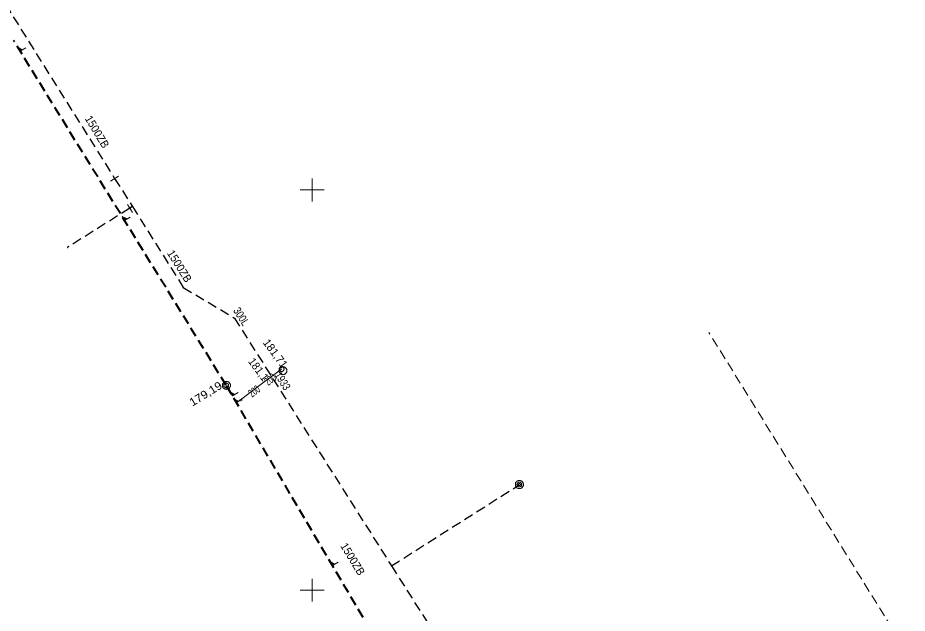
# Model space of a CAD drawing. Extents: x -740851 to -738888, y -1041382 to -1040235.
# Drawn here: x -739386.8 to -739275.6, y -1041102.9 to -1041028.5 of the extents above; entities that cross this region are included whole.
import ezdxf

# ---------------------------------------------------------------- set-up
doc = ezdxf.new("R2010")
doc.units = 0
doc.header["$LTSCALE"] = 0.4
doc.linetypes.add('MEDIUM_DASHED', pattern=[4.5, 3, -1.5])
for name, color, linetype, lineweight in [('1', 7, 'Continuous', 13), ('18', 7, 'Continuous', 13), ('38', 7, 'Continuous', 13), ('49', 7, 'Continuous', 13), ('8', 7, 'Continuous', 13)]:
    doc.layers.add(name, color=color, linetype=linetype, lineweight=lineweight)

msp = doc.modelspace()

# ---------------------------------------------------------------- linework, layer by layer
at = {"layer": '1'}
for p, q in [((-739350, -1041048.571), (-739350, -1041051.429)), ((-739351.48, -1041050), (-739348.48, -1041050)), ((-739350, -1041098.571), (-739350, -1041101.429)), ((-739351.48, -1041100), (-739348.48, -1041100))]:
    msp.add_line(p, q, dxfattribs=at)
at = {"layer": '18', "linetype": 'MEDIUM_DASHED', "lineweight": 40}
for p, q in [((-739360.74, -1041074.41), (-739387.32, -1041031.31)), ((-739332.66, -1041122.02), (-739360.74, -1041074.41))]:
    msp.add_line(p, q, dxfattribs=at)
at = {"layer": '18'}
for p, q in [((-739359.047, -1041076.171), (-739358.717, -1041076.255)), ((-739358.832, -1041076.051), (-739358.918, -1041076.384))]:
    msp.add_line(p, q, dxfattribs=at)
for points in [[(-739385.785, -1041032.241), (-739386.479, -1041032.669), (-739386.785, -1041032.174), (-739386.166, -1041032.476)], [(-739386.258, -1041032.482), (-739386.461, -1041032.607), (-739386.656, -1041032.291), (-739386.256, -1041032.486)], [(-739386.354, -1041032.491), (-739386.455, -1041032.553), (-739386.555, -1041032.391), (-739386.352, -1041032.494)], [(-739372.741, -1041053.392), (-739373.435, -1041053.82), (-739373.741, -1041053.325), (-739373.122, -1041053.627)], [(-739373.214, -1041053.634), (-739373.417, -1041053.758), (-739373.612, -1041053.442), (-739373.212, -1041053.637)], [(-739373.31, -1041053.642), (-739373.411, -1041053.705), (-739373.511, -1041053.542), (-739373.308, -1041053.646)], [(-739359.248, -1041075.327), (-739359.952, -1041075.742), (-739360.248, -1041075.24), (-739359.634, -1041075.555)], [(-739359.727, -1041075.56), (-739359.932, -1041075.681), (-739360.121, -1041075.36), (-739359.725, -1041075.563)], [(-739359.822, -1041075.566), (-739359.925, -1041075.627), (-739360.022, -1041075.462), (-739359.821, -1041075.57)], [(-739358.875, -1041076.214), (-739359.468, -1041076.564), (-739359.717, -1041076.141), (-739359.2, -1041076.406)], [(-739359.278, -1041076.41), (-739359.451, -1041076.512), (-739359.61, -1041076.242), (-739359.276, -1041076.413)], [(-739359.359, -1041076.416), (-739359.445, -1041076.467), (-739359.527, -1041076.328), (-739359.357, -1041076.419)], [(-739346.751, -1041096.516), (-739347.455, -1041096.932), (-739347.751, -1041096.429), (-739347.137, -1041096.744)], [(-739347.23, -1041096.749), (-739347.435, -1041096.87), (-739347.624, -1041096.549), (-739347.228, -1041096.752)], [(-739347.325, -1041096.756), (-739347.428, -1041096.816), (-739347.525, -1041096.651), (-739347.323, -1041096.759)]]:
    msp.add_lwpolyline(points, dxfattribs=at)
for points in [[(-739353.14, -1041072.58), (-739353.15, -1041072.53), (-739353.15, -1041072.48), (-739353.17, -1041072.43), (-739353.19, -1041072.38), (-739353.21, -1041072.33), (-739353.24, -1041072.29), (-739353.27, -1041072.25), (-739353.31, -1041072.21), (-739353.35, -1041072.18), (-739353.39, -1041072.15), (-739353.44, -1041072.13), (-739353.49, -1041072.11), (-739353.54, -1041072.09), (-739353.59, -1041072.09), (-739353.64, -1041072.08), (-739353.69, -1041072.09), (-739353.74, -1041072.09), (-739353.79, -1041072.11), (-739353.84, -1041072.13), (-739353.89, -1041072.15), (-739353.93, -1041072.18), (-739353.97, -1041072.21), (-739354.01, -1041072.25), (-739354.04, -1041072.29), (-739354.07, -1041072.33), (-739354.09, -1041072.38), (-739354.11, -1041072.43), (-739354.13, -1041072.48), (-739354.13, -1041072.53), (-739354.14, -1041072.58), (-739354.13, -1041072.63), (-739354.13, -1041072.68), (-739354.11, -1041072.73), (-739354.09, -1041072.78), (-739354.07, -1041072.83), (-739354.04, -1041072.87), (-739354.01, -1041072.91), (-739353.97, -1041072.95), (-739353.93, -1041072.98), (-739353.89, -1041073.01), (-739353.84, -1041073.03), (-739353.79, -1041073.05), (-739353.74, -1041073.07), (-739353.69, -1041073.07), (-739353.64, -1041073.08), (-739353.59, -1041073.07), (-739353.54, -1041073.07), (-739353.49, -1041073.05), (-739353.44, -1041073.03), (-739353.39, -1041073.01), (-739353.35, -1041072.98), (-739353.31, -1041072.95), (-739353.27, -1041072.91), (-739353.24, -1041072.87), (-739353.21, -1041072.83), (-739353.19, -1041072.78), (-739353.17, -1041072.73), (-739353.15, -1041072.68), (-739353.15, -1041072.63)], [(-739353.51, -1041072.38), (-739353.51, -1041072.35), (-739353.516, -1041072.32), (-739353.522, -1041072.29), (-739353.534, -1041072.26), (-739353.552, -1041072.23), (-739353.57, -1041072.206), (-739353.588, -1041072.182), (-739353.612, -1041072.158), (-739353.636, -1041072.14), (-739353.66, -1041072.122), (-739353.69, -1041072.104), (-739353.72, -1041072.092), (-739353.75, -1041072.086), (-739353.78, -1041072.08), (-739353.81, -1041072.08), (-739353.84, -1041072.08), (-739353.87, -1041072.086), (-739353.9, -1041072.092), (-739353.93, -1041072.104), (-739353.96, -1041072.122), (-739353.984, -1041072.14), (-739354.008, -1041072.158), (-739354.032, -1041072.182), (-739354.05, -1041072.206), (-739354.068, -1041072.23), (-739354.086, -1041072.26), (-739354.098, -1041072.29), (-739354.104, -1041072.32), (-739354.11, -1041072.35), (-739354.11, -1041072.38), (-739354.11, -1041072.41), (-739354.104, -1041072.44), (-739354.098, -1041072.47), (-739354.086, -1041072.5), (-739354.068, -1041072.53), (-739354.05, -1041072.554), (-739354.032, -1041072.578), (-739354.008, -1041072.602), (-739353.984, -1041072.62), (-739353.96, -1041072.638), (-739353.93, -1041072.656), (-739353.9, -1041072.668), (-739353.87, -1041072.674), (-739353.84, -1041072.68), (-739353.81, -1041072.68), (-739353.78, -1041072.68), (-739353.75, -1041072.674), (-739353.72, -1041072.668), (-739353.69, -1041072.656), (-739353.66, -1041072.638), (-739353.636, -1041072.62), (-739353.612, -1041072.602), (-739353.588, -1041072.578), (-739353.57, -1041072.554), (-739353.552, -1041072.53), (-739353.534, -1041072.5), (-739353.522, -1041072.47), (-739353.516, -1041072.44), (-739353.51, -1041072.41)], [(-739360.21, -1041074.42), (-739360.22, -1041074.37), (-739360.22, -1041074.32), (-739360.24, -1041074.27), (-739360.26, -1041074.22), (-739360.28, -1041074.17), (-739360.31, -1041074.13), (-739360.34, -1041074.09), (-739360.38, -1041074.05), (-739360.42, -1041074.02), (-739360.46, -1041073.99), (-739360.51, -1041073.97), (-739360.56, -1041073.95), (-739360.61, -1041073.93), (-739360.66, -1041073.93), (-739360.71, -1041073.92), (-739360.76, -1041073.93), (-739360.81, -1041073.93), (-739360.86, -1041073.95), (-739360.91, -1041073.97), (-739360.96, -1041073.99), (-739361, -1041074.02), (-739361.04, -1041074.05), (-739361.08, -1041074.09), (-739361.11, -1041074.13), (-739361.14, -1041074.17), (-739361.16, -1041074.22), (-739361.18, -1041074.27), (-739361.2, -1041074.32), (-739361.2, -1041074.37), (-739361.21, -1041074.42), (-739361.2, -1041074.47), (-739361.2, -1041074.52), (-739361.18, -1041074.57), (-739361.16, -1041074.62), (-739361.14, -1041074.67), (-739361.11, -1041074.71), (-739361.08, -1041074.75), (-739361.04, -1041074.79), (-739361, -1041074.82), (-739360.96, -1041074.85), (-739360.91, -1041074.87), (-739360.86, -1041074.89), (-739360.81, -1041074.91), (-739360.76, -1041074.91), (-739360.71, -1041074.92), (-739360.66, -1041074.91), (-739360.61, -1041074.91), (-739360.56, -1041074.89), (-739360.51, -1041074.87), (-739360.46, -1041074.85), (-739360.42, -1041074.82), (-739360.38, -1041074.79), (-739360.34, -1041074.75), (-739360.31, -1041074.71), (-739360.28, -1041074.67), (-739360.26, -1041074.62), (-739360.24, -1041074.57), (-739360.22, -1041074.52), (-739360.22, -1041074.47)], [(-739360.44, -1041074.41), (-739360.44, -1041074.38), (-739360.446, -1041074.35), (-739360.452, -1041074.32), (-739360.464, -1041074.29), (-739360.482, -1041074.26), (-739360.5, -1041074.236), (-739360.518, -1041074.212), (-739360.542, -1041074.188), (-739360.566, -1041074.17), (-739360.59, -1041074.152), (-739360.62, -1041074.134), (-739360.65, -1041074.122), (-739360.68, -1041074.116), (-739360.71, -1041074.11), (-739360.74, -1041074.11), (-739360.77, -1041074.11), (-739360.8, -1041074.116), (-739360.83, -1041074.122), (-739360.86, -1041074.134), (-739360.89, -1041074.152), (-739360.914, -1041074.17), (-739360.938, -1041074.188), (-739360.962, -1041074.212), (-739360.98, -1041074.236), (-739360.998, -1041074.26), (-739361.016, -1041074.29), (-739361.028, -1041074.32), (-739361.034, -1041074.35), (-739361.04, -1041074.38), (-739361.04, -1041074.41), (-739361.04, -1041074.44), (-739361.034, -1041074.47), (-739361.028, -1041074.5), (-739361.016, -1041074.53), (-739360.998, -1041074.56), (-739360.98, -1041074.584), (-739360.962, -1041074.608), (-739360.938, -1041074.632), (-739360.914, -1041074.65), (-739360.89, -1041074.668), (-739360.86, -1041074.686), (-739360.83, -1041074.698), (-739360.8, -1041074.704), (-739360.77, -1041074.71), (-739360.74, -1041074.71), (-739360.71, -1041074.71), (-739360.68, -1041074.704), (-739360.65, -1041074.698), (-739360.62, -1041074.686), (-739360.59, -1041074.668), (-739360.566, -1041074.65), (-739360.542, -1041074.632), (-739360.518, -1041074.608), (-739360.5, -1041074.584), (-739360.482, -1041074.56), (-739360.464, -1041074.53), (-739360.452, -1041074.5), (-739360.446, -1041074.47), (-739360.44, -1041074.44)]]:
    msp.add_lwpolyline(points, close=True, dxfattribs=at)
at = {"layer": '38', "linetype": 'MEDIUM_DASHED'}
msp.add_lwpolyline([(-739312.567, -1041134.418), (-739275.615, -1041107.811), (-739300.396, -1041067.826)], dxfattribs=at)
at = {"layer": '49'}
msp.add_line((-739353.81, -1041072.38), (-739356.02, -1041074.03), dxfattribs=at)
msp.add_lwpolyline([(-739356.02, -1041074.03), (-739359.29, -1041076.47), (-739359.47, -1041076.563)], dxfattribs=at)
at = {"layer": '8'}
for p, q in [((-739375.219, -1041048.903), (-739374.219, -1041048.272)), ((-739372.462, -1041052.823), (-739373.093, -1041051.823)), ((-739380.623, -1041057.155), (-739380.62, -1041057.16)), ((-739380.573, -1041057.235), (-739380.569, -1041057.24)), ((-739340.124, -1041097.015), (-739340.024, -1041096.915)), ((-739340.124, -1041096.915), (-739340.024, -1041097.015)), ((-739340.124, -1041096.915), (-739340.124, -1041096.935)), ((-739340.124, -1041096.915), (-739340.104, -1041096.915)), ((-739340.124, -1041097.015), (-739340.124, -1041096.995)), ((-739340.124, -1041097.015), (-739340.104, -1041097.015)), ((-739340.024, -1041096.915), (-739340.044, -1041096.915)), ((-739340.024, -1041097.015), (-739340.044, -1041097.015)), ((-739340.024, -1041096.915), (-739340.024, -1041096.935)), ((-739340.024, -1041097.015), (-739340.024, -1041096.995))]:
    msp.add_line(p, q, dxfattribs=at)
at = {"layer": '8', "linetype": 'MEDIUM_DASHED', "lineweight": 25}
for q in [(-739324.11, -1041086.84), (-739315.144, -1041136.272)]:
    msp.add_line((-739340.075, -1041096.966), q, dxfattribs=at)
for points in [[(-739496.554, -1040855.122), (-739491.67, -1040862.2), (-739374.679, -1041048.562)], [(-739374.679, -1041048.562), (-739372.467, -1041052.071), (-739366.097, -1041062.177), (-739359.713, -1041066.006), (-739340.075, -1041096.966)], [(-739372.467, -1041052.071), (-739372.803, -1041052.283), (-739380.554, -1041057.169)]]:
    msp.add_lwpolyline(points, dxfattribs=at)
at = {"layer": '8'}
for points in [[(-739380.569, -1041057.24), (-739380.565, -1041057.237), (-739380.562, -1041057.234), (-739380.558, -1041057.23), (-739380.555, -1041057.226), (-739380.552, -1041057.22), (-739380.55, -1041057.216), (-739380.548, -1041057.211), (-739380.547, -1041057.206), (-739380.547, -1041057.201), (-739380.546, -1041057.196), (-739380.547, -1041057.19), (-739380.548, -1041057.185), (-739380.549, -1041057.18), (-739380.551, -1041057.175), (-739380.554, -1041057.171), (-739380.556, -1041057.167), (-739380.56, -1041057.163), (-739380.564, -1041057.159), (-739380.568, -1041057.156), (-739380.573, -1041057.153), (-739380.578, -1041057.152), (-739380.582, -1041057.15), (-739380.588, -1041057.149), (-739380.593, -1041057.148), (-739380.598, -1041057.148), (-739380.604, -1041057.148), (-739380.609, -1041057.149), (-739380.614, -1041057.151), (-739380.619, -1041057.152), (-739380.623, -1041057.155)], [(-739380.573, -1041057.235), (-739380.568, -1041057.232), (-739380.566, -1041057.229), (-739380.562, -1041057.226), (-739380.56, -1041057.222), (-739380.557, -1041057.218), (-739380.555, -1041057.214), (-739380.553, -1041057.209), (-739380.552, -1041057.205), (-739380.552, -1041057.2), (-739380.552, -1041057.196), (-739380.553, -1041057.191), (-739380.553, -1041057.187), (-739380.555, -1041057.182), (-739380.556, -1041057.178), (-739380.559, -1041057.174), (-739380.562, -1041057.17), (-739380.565, -1041057.167), (-739380.568, -1041057.163), (-739380.572, -1041057.161), (-739380.576, -1041057.159), (-739380.58, -1041057.156), (-739380.584, -1041057.154), (-739380.588, -1041057.154), (-739380.593, -1041057.153), (-739380.598, -1041057.154), (-739380.602, -1041057.154), (-739380.607, -1041057.154), (-739380.611, -1041057.156), (-739380.615, -1041057.158), (-739380.62, -1041057.16)]]:
    msp.add_lwpolyline(points, dxfattribs=at)
for points in [[(-739323.595, -1041086.81), (-739323.595, -1041086.764), (-739323.595, -1041086.704), (-739323.611, -1041086.658), (-739323.626, -1041086.597), (-739323.656, -1041086.552), (-739323.686, -1041086.507), (-739323.717, -1041086.476), (-739323.762, -1041086.431), (-739323.792, -1041086.401), (-739323.838, -1041086.37), (-739323.883, -1041086.34), (-739323.944, -1041086.325), (-739323.989, -1041086.31), (-739324.05, -1041086.31), (-739324.095, -1041086.31), (-739324.156, -1041086.31), (-739324.201, -1041086.31), (-739324.247, -1041086.325), (-739324.307, -1041086.34), (-739324.353, -1041086.37), (-739324.398, -1041086.401), (-739324.429, -1041086.431), (-739324.474, -1041086.476), (-739324.504, -1041086.507), (-739324.535, -1041086.552), (-739324.565, -1041086.597), (-739324.58, -1041086.658), (-739324.595, -1041086.704), (-739324.595, -1041086.764), (-739324.595, -1041086.81), (-739324.595, -1041086.87), (-739324.595, -1041086.916), (-739324.58, -1041086.961), (-739324.565, -1041087.022), (-739324.535, -1041087.067), (-739324.504, -1041087.113), (-739324.474, -1041087.143), (-739324.429, -1041087.188), (-739324.398, -1041087.219), (-739324.353, -1041087.249), (-739324.307, -1041087.279), (-739324.247, -1041087.294), (-739324.201, -1041087.31), (-739324.156, -1041087.31), (-739324.095, -1041087.31), (-739324.05, -1041087.31), (-739323.989, -1041087.31), (-739323.944, -1041087.294), (-739323.883, -1041087.279), (-739323.838, -1041087.249), (-739323.792, -1041087.219), (-739323.762, -1041087.188), (-739323.717, -1041087.143), (-739323.686, -1041087.113), (-739323.656, -1041087.067), (-739323.626, -1041087.022), (-739323.611, -1041086.961), (-739323.595, -1041086.916), (-739323.595, -1041086.87)], [(-739323.792, -1041086.81), (-739323.792, -1041086.779), (-739323.807, -1041086.749), (-739323.807, -1041086.719), (-739323.823, -1041086.688), (-739323.838, -1041086.658), (-739323.853, -1041086.628), (-739323.868, -1041086.613), (-739323.898, -1041086.582), (-739323.914, -1041086.567), (-739323.944, -1041086.552), (-739323.974, -1041086.537), (-739324.004, -1041086.522), (-739324.035, -1041086.522), (-739324.065, -1041086.507), (-739324.095, -1041086.507), (-739324.126, -1041086.507), (-739324.156, -1041086.522), (-739324.186, -1041086.522), (-739324.217, -1041086.537), (-739324.247, -1041086.552), (-739324.277, -1041086.567), (-739324.292, -1041086.582), (-739324.323, -1041086.613), (-739324.338, -1041086.628), (-739324.353, -1041086.658), (-739324.368, -1041086.688), (-739324.383, -1041086.719), (-739324.383, -1041086.749), (-739324.398, -1041086.779), (-739324.398, -1041086.81), (-739324.398, -1041086.84), (-739324.383, -1041086.87), (-739324.383, -1041086.901), (-739324.368, -1041086.931), (-739324.353, -1041086.961), (-739324.338, -1041086.991), (-739324.323, -1041087.007), (-739324.292, -1041087.037), (-739324.277, -1041087.052), (-739324.247, -1041087.067), (-739324.217, -1041087.082), (-739324.186, -1041087.097), (-739324.156, -1041087.097), (-739324.126, -1041087.113), (-739324.095, -1041087.113), (-739324.065, -1041087.113), (-739324.035, -1041087.097), (-739324.004, -1041087.097), (-739323.974, -1041087.082), (-739323.944, -1041087.067), (-739323.914, -1041087.052), (-739323.898, -1041087.037), (-739323.868, -1041087.007), (-739323.853, -1041086.991), (-739323.838, -1041086.961), (-739323.823, -1041086.931), (-739323.807, -1041086.901), (-739323.807, -1041086.87), (-739323.792, -1041086.84)], [(-739323.959, -1041086.81), (-739323.959, -1041086.794), (-739323.974, -1041086.779), (-739323.974, -1041086.764), (-739323.974, -1041086.749), (-739323.989, -1041086.749), (-739323.989, -1041086.734), (-739324.004, -1041086.719), (-739324.02, -1041086.704), (-739324.035, -1041086.704), (-739324.035, -1041086.688), (-739324.05, -1041086.688), (-739324.065, -1041086.688), (-739324.08, -1041086.673), (-739324.095, -1041086.673), (-739324.111, -1041086.673), (-739324.126, -1041086.688), (-739324.141, -1041086.688), (-739324.156, -1041086.688), (-739324.156, -1041086.704), (-739324.171, -1041086.704), (-739324.186, -1041086.719), (-739324.201, -1041086.734), (-739324.217, -1041086.749), (-739324.217, -1041086.764), (-739324.217, -1041086.779), (-739324.232, -1041086.794), (-739324.232, -1041086.81), (-739324.232, -1041086.825), (-739324.217, -1041086.84), (-739324.217, -1041086.855), (-739324.217, -1041086.87), (-739324.201, -1041086.885), (-739324.186, -1041086.901), (-739324.171, -1041086.916), (-739324.156, -1041086.931), (-739324.141, -1041086.931), (-739324.126, -1041086.931), (-739324.111, -1041086.946), (-739324.095, -1041086.946), (-739324.08, -1041086.946), (-739324.065, -1041086.931), (-739324.05, -1041086.931), (-739324.035, -1041086.931), (-739324.02, -1041086.916), (-739324.004, -1041086.901), (-739323.989, -1041086.885), (-739323.989, -1041086.87), (-739323.974, -1041086.87), (-739323.974, -1041086.855), (-739323.974, -1041086.84), (-739323.959, -1041086.825)], [(-739340.024, -1041096.965), (-739340.024, -1041096.96), (-739340.025, -1041096.955), (-739340.026, -1041096.95), (-739340.028, -1041096.945), (-739340.031, -1041096.94), (-739340.034, -1041096.936), (-739340.037, -1041096.932), (-739340.041, -1041096.928), (-739340.045, -1041096.925), (-739340.049, -1041096.922), (-739340.054, -1041096.919), (-739340.059, -1041096.917), (-739340.064, -1041096.916), (-739340.069, -1041096.915), (-739340.074, -1041096.915), (-739340.079, -1041096.915), (-739340.084, -1041096.916), (-739340.089, -1041096.917), (-739340.094, -1041096.919), (-739340.099, -1041096.922), (-739340.103, -1041096.925), (-739340.107, -1041096.928), (-739340.111, -1041096.932), (-739340.114, -1041096.936), (-739340.117, -1041096.94), (-739340.12, -1041096.945), (-739340.122, -1041096.95), (-739340.123, -1041096.955), (-739340.124, -1041096.96), (-739340.124, -1041096.965), (-739340.124, -1041096.97), (-739340.123, -1041096.975), (-739340.122, -1041096.98), (-739340.12, -1041096.985), (-739340.117, -1041096.99), (-739340.114, -1041096.994), (-739340.111, -1041096.998), (-739340.107, -1041097.002), (-739340.103, -1041097.005), (-739340.099, -1041097.008), (-739340.094, -1041097.011), (-739340.089, -1041097.013), (-739340.084, -1041097.014), (-739340.079, -1041097.015), (-739340.074, -1041097.015), (-739340.069, -1041097.015), (-739340.064, -1041097.014), (-739340.059, -1041097.013), (-739340.054, -1041097.011), (-739340.049, -1041097.008), (-739340.045, -1041097.005), (-739340.041, -1041097.002), (-739340.037, -1041096.998), (-739340.034, -1041096.994), (-739340.031, -1041096.99), (-739340.028, -1041096.985), (-739340.026, -1041096.98), (-739340.025, -1041096.975), (-739340.024, -1041096.97)]]:
    msp.add_lwpolyline(points, close=True, dxfattribs=at)

# ---------------------------------------------------------------- texts
at = {"layer": '18'}
for s, rotation, width, p in [('1500ZB', 301.067, 0.95, (-739378.45, -1041041.084)), ('1500ZB', 302.066, 0.95, (-739368.176, -1041057.901)), ('181,1', 306.73, 0.95, (-739358.05, -1041071.446)), ('200', 36.744, 0.5, (-739355.496, -1041074.489)), ('179,19', 31.759, 1.1, (-739364.958, -1041077.075)), ('200', 36.728, 0.5, (-739357.498, -1041075.955)), ('1500ZB', 301.458, 0.95, (-739346.509, -1041094.482))]:
    msp.add_text(s, height=1, rotation=rotation, dxfattribs=dict(at, width=width)).set_placement(p)
msp.add_text('181,71', height=1, rotation=306.745, dxfattribs=at).set_placement((-739356.213, -1041069.088))
at = {"layer": '8', "width": 0.8}
for s, p in [('300L', (-739359.91, -1041065.074)), ('1933', (-739354.737, -1041073.126))]:
    msp.add_text(s, height=1, rotation=302.387, dxfattribs=at).set_placement(p)

doc.saveas('drawing.dxf')
